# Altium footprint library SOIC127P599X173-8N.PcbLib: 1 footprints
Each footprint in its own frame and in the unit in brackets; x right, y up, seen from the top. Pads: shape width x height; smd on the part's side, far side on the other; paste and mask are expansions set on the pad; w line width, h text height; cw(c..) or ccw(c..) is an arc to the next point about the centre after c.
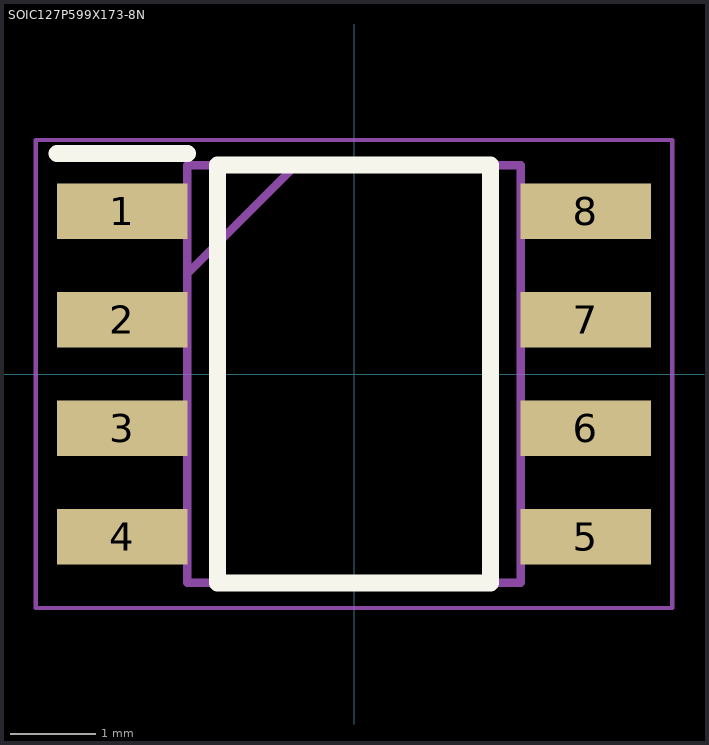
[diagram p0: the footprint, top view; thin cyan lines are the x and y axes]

## SOIC127P599X173-8N [mm]
pads (8):
  rect 1.525x0.65 smd: 1(-2.712,1.905) 2(-2.712,0.635) 3(-2.712,-0.635) 4(-2.712,-1.905) 5(2.712,-1.905) 6(2.712,-0.635) 7(2.712,0.635) 8(2.712,1.905)
Top Overlay:
  lines w0.2: -3.475,2.58 -1.95,2.58 ; -1.6,-2.445 1.6,-2.445 1.6,2.445 -1.6,2.445 -1.6,-2.445
Mechanical 15:
  lines w0.1: -1.95,1.175 -0.68,2.445 ; -1.95,-2.445 1.95,-2.445 1.95,2.445 -1.95,2.445 -1.95,-2.445
Mechanical 20:
  lines w0.05: -3.725,-2.74 3.725,-2.74 3.725,2.74 -3.725,2.74 -3.725,-2.74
